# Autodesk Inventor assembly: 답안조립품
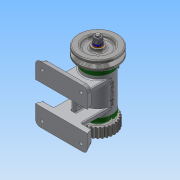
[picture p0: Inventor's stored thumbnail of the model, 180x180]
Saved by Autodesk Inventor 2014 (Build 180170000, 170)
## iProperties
Created: 2016-07
Part Number: 답안조립품
Document SubType Name: Assembly
Designer: 406-8
Author: 406-8
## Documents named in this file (16)
- C:\Users\406-8\Desktop\답안조립품.iam
- C:\Users\406-8\Desktop\1.본체.ipt
- C:\Users\406-8\Desktop\460707V1008\V벨트풀리.ipt
- C:\Users\406-8\Desktop\460707V1008\너트 M 8.ipt
- C:\Users\406-8\Desktop\460707V1008\니플 M 6 x 0.75.ipt
- C:\Users\406-8\Desktop\460707V1008\베어링 15 x 32 x 9.ipt
- C:\Users\406-8\Desktop\460707V1008\볼트 M 6 x 8.ipt
- C:\Users\406-8\Desktop\460707V1008\볼트 M4 x 12.ipt
- C:\Users\406-8\Desktop\460707V1008\스퍼기어.ipt
- C:\Users\406-8\Desktop\460707V1008\스프링와셔 8.ipt
- C:\Users\406-8\Desktop\460707V1008\오일 실 15 25 7.ipt
- C:\Users\406-8\Desktop\460707V1008\와셔 6x11.5.ipt
- C:\Users\406-8\Desktop\460707V1008\와셔 8x17.ipt
- C:\Users\406-8\Desktop\460707V1008\축.ipt
- C:\Users\406-8\Desktop\460707V1008\커버.ipt
- C:\Users\406-8\Desktop\460707V1008\키 3 x 3 x 12.ipt
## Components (12 placed, 4 different names)
1. 1.본체:1
2. V벨트풀리:1
3. KS B 2023 6002 - 15 x 32 x 9:1
4. KS B 2023 6002 - 15 x 32 x 9:2
5. ISO 4762 M4 x 12:1
6. ISO 4762 M4 x 12:3
7. ISO 4762 M4 x 12:4
8. ISO 4762 M4 x 12:5
9. ISO 4762 M4 x 12:2
10. ISO 4762 M4 x 12:6
11. ISO 4762 M4 x 12:7
12. ISO 4762 M4 x 12:8
## Named parameters: d2_d1 = 0, d3_d0 = 0, d28_d26 = 0, d29_d27 = 0
